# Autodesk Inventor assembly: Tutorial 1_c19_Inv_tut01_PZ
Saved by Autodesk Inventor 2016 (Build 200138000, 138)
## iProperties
Created: 2015-04
Part Number: Tutorial 1_c19_Inv_tut01_PZ
Document SubType Name: Assembly
Designer: Sandeep
Author: Sandeep
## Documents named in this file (3)
- C:\Autodesk Inventor 2016\c19\Tutorial 1_c19_Inv_tut01_PZ.iam
- C:\Autodesk Inventor 2016\c19\Tutorial 1_c19_Inv_tut01_MP.ipt
- C:\Autodesk Inventor 2016\c19\Tutorial 1_c19_Inv_tut01_WP.ipt
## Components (2 placed, 2 different names)
1. Tutorial 1_c19_Inv_tut01_MP:1 — Flush:1, Flush:2, Flush:3, Flush:4, Flush:5, Flush:6
2. Tutorial 1_c19_Inv_tut01_WP:1 — Flush:4, Flush:5, Flush:6
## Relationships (6: Flush 6)
- Flush:1: Tutorial 1_c19_Inv_tut01_MP:1
- Flush:2: Tutorial 1_c19_Inv_tut01_MP:1
- Flush:3: Tutorial 1_c19_Inv_tut01_MP:1
- Flush:4: Tutorial 1_c19_Inv_tut01_MP:1 ↔ Tutorial 1_c19_Inv_tut01_WP:1
- Flush:5: Tutorial 1_c19_Inv_tut01_MP:1 ↔ Tutorial 1_c19_Inv_tut01_WP:1
- Flush:6: Tutorial 1_c19_Inv_tut01_MP:1 ↔ Tutorial 1_c19_Inv_tut01_WP:1
